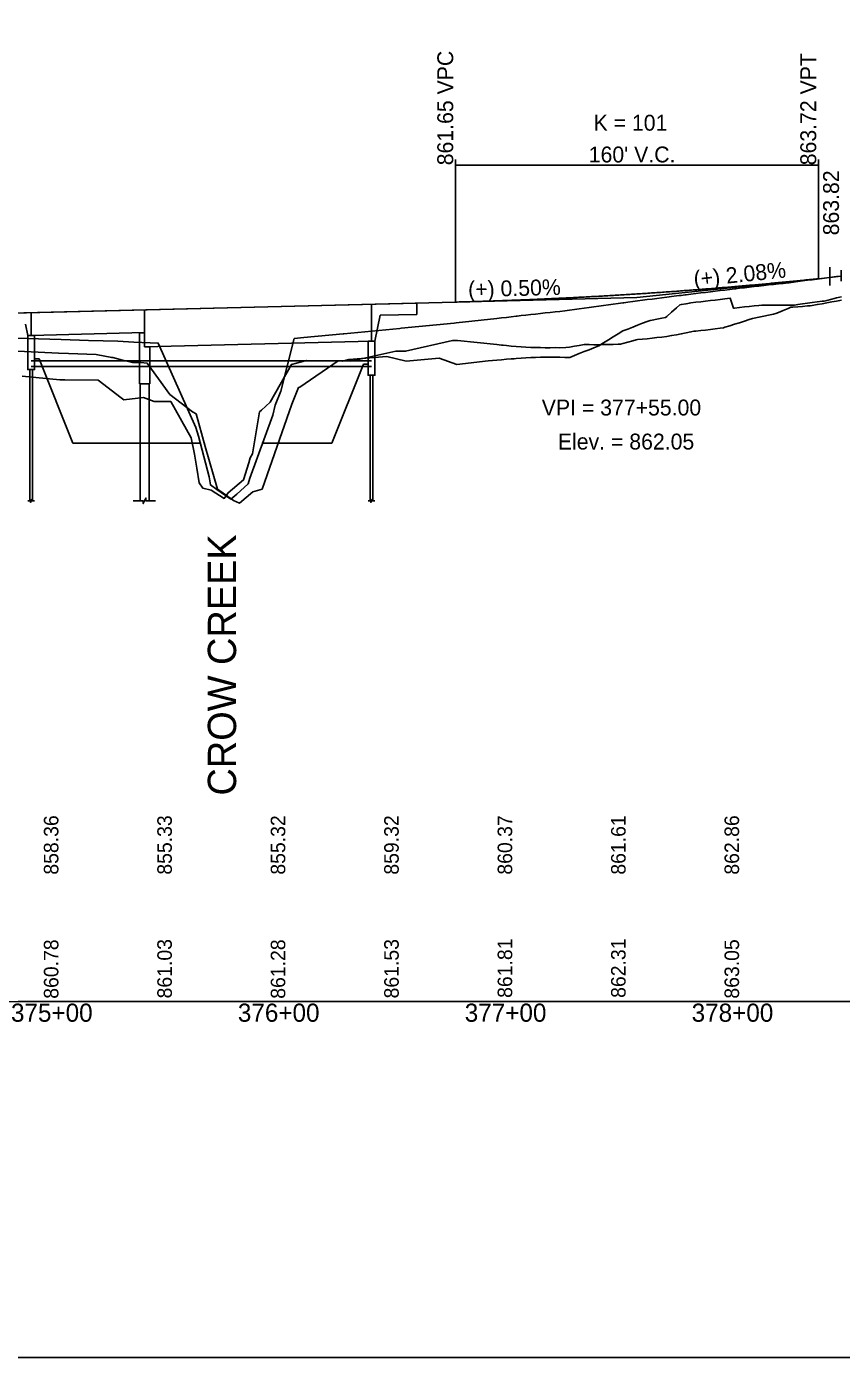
# Model space of a CAD drawing. Extents: x 1459978 to 1464152, y 1125650 to 1128602.
# Drawn here: x 1461940 to 1462299, y 1127502 to 1128089 of the extents above; entities that cross this region are included whole.
import ezdxf

# ---------------------------------------------------------------- set-up
doc = ezdxf.new("R2010")
doc.units = 0
for name, color, linetype in [('BR_CONCRETE', 7, 'Continuous'), ('BR_EXIST_GROUND_LT', 7, 'Continuous'), ('BR_EXIST_GROUND_RT', 7, 'Continuous'), ('BR_GROUND LINES', 7, 'Continuous'), ('BR_USER NOTES', 7, 'Continuous'), ('RD_DDB_GradeTX', 7, 'Continuous'), ('RD_DDB_Profile_EX', 7, 'Continuous'), ('RD_DDB_Profile_Lbl', 7, 'Continuous'), ('RD_DDB_Profile_PR', 7, 'Continuous'), ('RD_DDB_StaTX', 7, 'Continuous'), ('RD_DDB_StripGrade', 7, 'Continuous'), ('RD_DDB_VCLbl', 7, 'Continuous'), ('RD_GPK_Profile_Cell', 7, 'Continuous'), ('RD_SHT_ShtClip', 7, 'Continuous'), ('RD_SHT_TX', 7, 'Continuous')]:
    doc.layers.add(name, color=color, linetype=linetype)

msp = doc.modelspace()

# ---------------------------------------------------------------- linework, layer by layer
at = {"layer": 'BR_CONCRETE'}
for p, q in [((1461921.69, 1127962.22), (1462111.69, 1127966.97)), ((1461941.69, 1127952.72), (1461941.69, 1127962.72)), ((1461991.69, 1127947.72), (1461991.69, 1127963.97)), ((1462091.69, 1127950.22), (1462091.69, 1127966.47)), ((1462093.19, 1127950.14), (1462095.48, 1127961.57)), ((1462095.48, 1127961.57), (1462111.69, 1127961.97)), ((1462111.69, 1127966.97), (1462111.69, 1127961.97)), ((1461940.19, 1127952.64), (1461939.19, 1127957.66)), ((1461941.69, 1127952.72), (1461991.69, 1127953.97)), ((1461941.69, 1127952.72), (1461941.69, 1127952.64)), ((1461991.69, 1127947.72), (1462091.69, 1127950.22)), ((1462091.69, 1127950.22), (1462091.69, 1127950.14)), ((1461941.11, 1127937.4), (1461941.11, 1127879.76)), ((1461942.27, 1127937.4), (1461942.27, 1127879.76)), ((1462091.11, 1127935.14), (1462091.11, 1127879.76)), ((1462092.27, 1127935.14), (1462092.27, 1127879.76)), ((1461989.69, 1127879.76), (1461989.69, 1127931.39)), ((1461993.69, 1127879.76), (1461993.69, 1127931.39))]:
    msp.add_line(p, q, dxfattribs=at)
for points in [[(1461940.19, 1127952.64), (1461943.19, 1127952.64), (1461943.19, 1127937.64), (1461940.19, 1127937.64)], [(1461991.69, 1127947.64), (1461993.94, 1127947.64), (1461993.94, 1127931.39), (1461989.44, 1127931.39), (1461989.44, 1127953.86), (1461991.69, 1127953.86)], [(1462093.19, 1127950.14), (1462090.19, 1127950.14), (1462090.19, 1127935.14), (1462093.19, 1127935.14)]]:
    msp.add_lwpolyline(points, close=True, dxfattribs=at)
for points in [[(1461940.19, 1127879.76), (1461941.35, 1127879.76), (1461941.35, 1127879.07), (1461942.04, 1127880.46), (1461942.04, 1127879.76), (1461943.2, 1127879.76)], [(1461986.7, 1127879.76), (1461991.09, 1127879.76), (1461991.09, 1127878.56), (1461992.29, 1127880.96), (1461992.29, 1127879.76), (1461996.55, 1127879.76)], [(1462090.19, 1127879.76), (1462091.35, 1127879.76), (1462091.35, 1127879.07), (1462092.04, 1127880.46), (1462092.04, 1127879.76), (1462093.2, 1127879.76)]]:
    msp.add_lwpolyline(points, dxfattribs=at)
at = {"layer": 'BR_EXIST_GROUND_LT'}
msp.add_lwpolyline([(1461932.79, 1127945.88), (1461953.77, 1127944.88), (1461958.1, 1127944.67), (1461970.3, 1127944.33), (1461977.18, 1127942.96), (1461977.7, 1127942.94), (1461980.91, 1127942.11), (1461986.37, 1127940.81), (1461990, 1127940.72), (1461992.84, 1127940.43), (1462002.81, 1127926.71), (1462012.8, 1127918.95), (1462014.39, 1127918.07), (1462018.42, 1127903.69), (1462023.82, 1127884.85), (1462030.8, 1127879.93), (1462033.53, 1127878.8), (1462039.35, 1127883.8), (1462043.47, 1127884.98), (1462056.56, 1127922.32), (1462059.52, 1127929.8), (1462060.13, 1127929.88), (1462077.06, 1127941.53), (1462082.56, 1127941.39), (1462102.39, 1127945.74), (1462106.74, 1127945.71), (1462127.45, 1127950.42), (1462129.63, 1127950.45), (1462146.9, 1127948.65), (1462149.04, 1127948.43), (1462149.75, 1127948.36), (1462151.18, 1127948.19), (1462153.32, 1127947.96), (1462155.46, 1127947.76), (1462157.6, 1127947.62), (1462159.74, 1127947.51), (1462161.88, 1127947.42), (1462164.02, 1127947.35), (1462166.16, 1127947.3), (1462168.3, 1127947.28), (1462170.44, 1127947.28), (1462172.58, 1127947.3), (1462174.72, 1127947.29), (1462177.35, 1127947.31), (1462179, 1127947.57), (1462181.14, 1127947.93), (1462183.28, 1127948.31), (1462185.42, 1127948.68), (1462187.56, 1127948.64), (1462189.7, 1127948.62), (1462191.83, 1127948.62), (1462193.97, 1127948.64), (1462196.11, 1127948.68), (1462198.25, 1127948.74), (1462200.39, 1127948.82), (1462201.39, 1127948.87), (1462202.53, 1127949.17), (1462204.67, 1127949.76), (1462206.81, 1127950.36), (1462208.31, 1127950.8), (1462208.95, 1127950.85), (1462211.09, 1127951.04), (1462213.23, 1127951.25), (1462215.37, 1127951.49), (1462217.51, 1127951.74), (1462219.65, 1127952), (1462221.79, 1127952.29), (1462223.93, 1127952.6), (1462226.07, 1127952.98), (1462228.21, 1127953.38), (1462230.35, 1127953.79), (1462232.49, 1127954.22), (1462233.8, 1127954.5), (1462234.63, 1127954.58), (1462236.77, 1127954.81), (1462238.91, 1127955.06), (1462241.05, 1127955.32), (1462243.19, 1127955.6), (1462245.33, 1127955.9), (1462246.77, 1127956.11), (1462247.47, 1127956.31), (1462249.61, 1127956.96), (1462251.75, 1127957.62), (1462253.89, 1127958.3), (1462256.03, 1127958.99), (1462258.17, 1127959.7), (1462259.6, 1127960.19), (1462260.31, 1127960.32), (1462262.44, 1127960.74), (1462264.58, 1127961.18), (1462266.72, 1127961.63), (1462268.86, 1127962.09), (1462269.89, 1127962.32), (1462271, 1127962.79), (1462273.14, 1127963.7), (1462275.28, 1127964.62), (1462276.49, 1127965.12), (1462277.42, 1127965.18), (1462279.56, 1127965.33), (1462281.7, 1127965.5), (1462283.84, 1127965.69), (1462285.01, 1127965.79), (1462285.98, 1127965.95), (1462288.12, 1127966.31), (1462290.26, 1127966.68), (1462292.4, 1127967.07), (1462294.54, 1127967.46), (1462296.68, 1127967.87), (1462298.82, 1127968.29)], dxfattribs=at)
at = {"layer": 'BR_EXIST_GROUND_RT'}
msp.add_lwpolyline([(1461937.73, 1127934.7), (1461954.37, 1127933.18), (1461956.53, 1127933.17), (1461971.19, 1127932.99), (1461981.39, 1127925.22), (1461982.57, 1127924.33), (1461991.26, 1127925.32), (1461995.85, 1127923.63), (1462003.22, 1127923.6), (1462012.18, 1127907.51), (1462013.63, 1127900.38), (1462014.67, 1127894.14), (1462015.69, 1127887.65), (1462017.34, 1127885.37), (1462021.03, 1127884.54), (1462026.81, 1127880.86), (1462028.49, 1127883.34), (1462035.34, 1127889), (1462037.65, 1127896.48), (1462038.22, 1127898.7), (1462039.19, 1127900.5), (1462042.33, 1127918.96), (1462043.24, 1127919.74), (1462047.06, 1127923.23), (1462056.47, 1127939.95), (1462063.11, 1127941.71), (1462078.98, 1127941.36), (1462081.71, 1127942.08), (1462098.5, 1127943.39), (1462106.93, 1127941.38), (1462121.54, 1127942.66), (1462129.28, 1127939.92), (1462143.08, 1127941.47), (1462146.9, 1127941.82), (1462149.04, 1127942), (1462151.18, 1127942.16), (1462153.32, 1127942.31), (1462154.5, 1127942.38), (1462155.46, 1127942.46), (1462157.6, 1127942.62), (1462159.74, 1127942.77), (1462161.88, 1127942.9), (1462164.02, 1127943.01), (1462166.16, 1127943.11), (1462167.29, 1127943.15), (1462168.3, 1127943.16), (1462170.44, 1127943.15), (1462172.58, 1127943.13), (1462174.72, 1127943.09), (1462176.86, 1127943.03), (1462179.12, 1127942.95), (1462181.14, 1127943.8), (1462183.28, 1127944.68), (1462185.42, 1127945.54), (1462187.56, 1127946.39), (1462189.7, 1127947.22), (1462191.83, 1127948.09), (1462193.97, 1127949.43), (1462196.11, 1127950.75), (1462198.25, 1127952.06), (1462200.39, 1127953.37), (1462202.53, 1127954.67), (1462204.67, 1127955.44), (1462206.81, 1127956.29), (1462208.95, 1127957.26), (1462209.66, 1127957.58), (1462211.09, 1127958.07), (1462213.23, 1127958.8), (1462214.45, 1127959.21), (1462215.37, 1127959.4), (1462217.51, 1127959.84), (1462219.65, 1127960.27), (1462221.26, 1127960.6), (1462221.79, 1127961.07), (1462223.93, 1127962.94), (1462226.07, 1127964.82), (1462227.61, 1127966.18), (1462228.21, 1127966.29), (1462230.35, 1127966.69), (1462231.83, 1127966.96), (1462232.49, 1127967.04), (1462234.63, 1127967.29), (1462236.77, 1127967.54), (1462238.91, 1127967.79), (1462241.05, 1127968.04), (1462243.19, 1127968.3), (1462245.33, 1127968.55), (1462247.47, 1127968.81), (1462249.79, 1127969.09), (1462251.18, 1127964.72), (1462251.75, 1127964.78), (1462253.89, 1127965.02), (1462256.03, 1127965.25), (1462258.17, 1127965.48), (1462260.31, 1127965.7), (1462262.44, 1127965.92), (1462263.72, 1127966.05), (1462264.58, 1127966.05), (1462266.72, 1127966.07), (1462268.86, 1127966.08), (1462271, 1127966.08), (1462273.14, 1127966.08), (1462275.28, 1127966.08), (1462276.39, 1127966.07), (1462277.42, 1127966.07), (1462278.09, 1127966.06), (1462279.56, 1127966.27), (1462281.7, 1127966.57), (1462283.84, 1127966.87), (1462285.98, 1127967.16), (1462288.12, 1127967.45), (1462290.26, 1127967.73), (1462291.2, 1127967.85), (1462292.4, 1127968.16), (1462294.54, 1127968.7), (1462296.68, 1127969.25), (1462298.82, 1127969.78)], dxfattribs=at)
at = {"layer": 'BR_GROUND LINES'}
for p, q in [((1461943.19, 1127942.4), (1461945.19, 1127942.4)), ((1461945.19, 1127942.4), (1461960.04, 1127905.21)), ((1462088.19, 1127940.05), (1462074.26, 1127905.21)), ((1462090.19, 1127940.05), (1462088.19, 1127940.05)), ((1461960.04, 1127905.21), (1462016.39, 1127905.21)), ((1462043.37, 1127905.21), (1462074.26, 1127905.21))]:
    msp.add_line(p, q, dxfattribs=at)
at = {"layer": 'BR_USER NOTES'}
for p, q in [((1462293.69, 1127982.83), (1462293.69, 1127974.64)), ((1462298.69, 1127981.41), (1462298.69, 1127976.66)), ((1462293.69, 1127978.23), (1462298.69, 1127978.85)), ((1461941.69, 1127941.47), (1462091.69, 1127941.47)), ((1461941.69, 1127938.97), (1462091.69, 1127938.97))]:
    msp.add_line(p, q, dxfattribs=at)
at = {"layer": 'RD_DDB_GradeTX'}
for p in [(1462288.26, 1127977.67), (1462128.72, 1127967.4)]:
    msp.add_line(p, (1462208.69, 1127969.4), dxfattribs=at)
at = {"layer": 'RD_DDB_Profile_EX'}
msp.add_lwpolyline([(1461930.08, 1127951.68), (1461954.92, 1127950.9), (1461967, 1127950.52), (1461979.95, 1127950.11), (1461987, 1127949.79), (1461997.7, 1127949.31), (1462014.2, 1127912.05), (1462015.37, 1127908.21), (1462020.16, 1127890.3), (1462020.69, 1127886.78), (1462023.48, 1127884.83), (1462029.7, 1127880.53), (1462032.39, 1127882.69), (1462037.31, 1127887.34), (1462038.06, 1127889.81), (1462048.19, 1127917.6), (1462049.2, 1127921.95), (1462051.74, 1127928.12), (1462057.67, 1127951.32), (1462061.84, 1127951.72), (1462079.14, 1127953.35), (1462079.53, 1127953.39), (1462104.13, 1127955.76), (1462104.75, 1127955.83), (1462128.1, 1127958.09), (1462129.03, 1127958.21), (1462146.9, 1127960.19), (1462149.04, 1127960.43), (1462151.18, 1127960.67), (1462153.32, 1127960.91), (1462155.46, 1127961.19), (1462155.89, 1127961.24), (1462157.6, 1127961.43), (1462159.74, 1127961.67), (1462161.88, 1127961.9), (1462164.02, 1127962.14), (1462166.16, 1127962.37), (1462168.3, 1127962.61), (1462170.44, 1127962.84), (1462172.58, 1127963.07), (1462174.72, 1127963.3), (1462176.86, 1127963.54), (1462177.95, 1127963.65), (1462179, 1127963.81), (1462181.14, 1127964.14), (1462183.28, 1127964.43), (1462185.42, 1127964.72), (1462187.56, 1127965.01), (1462189.7, 1127965.3), (1462191.83, 1127965.59), (1462193.97, 1127965.88), (1462196.11, 1127966.16), (1462198.25, 1127966.45), (1462200.39, 1127966.73), (1462202.53, 1127967.01), (1462202.92, 1127967.06), (1462204.67, 1127967.32), (1462206.81, 1127967.64), (1462208.95, 1127967.92), (1462211.09, 1127968.19), (1462213.23, 1127968.47), (1462215.37, 1127968.74), (1462217.51, 1127969.01), (1462219.65, 1127969.28), (1462221.79, 1127969.55), (1462223.93, 1127969.82), (1462226.07, 1127970.09), (1462227.25, 1127970.24), (1462228.21, 1127970.36), (1462229.97, 1127970.58), (1462230.35, 1127970.63), (1462232.49, 1127970.89), (1462234.63, 1127971.16), (1462236.77, 1127971.42), (1462238.91, 1127971.68), (1462241.05, 1127971.94), (1462243.19, 1127972.2), (1462245.33, 1127972.45), (1462247.47, 1127972.71), (1462249.61, 1127972.96), (1462251.75, 1127973.21), (1462252.21, 1127973.27), (1462253.89, 1127973.47), (1462255.39, 1127973.65), (1462256.03, 1127973.72), (1462258.17, 1127973.97), (1462260.31, 1127974.21), (1462262.44, 1127974.45), (1462264.58, 1127974.7), (1462266.72, 1127974.94), (1462268.86, 1127975.18), (1462271, 1127975.41), (1462273.14, 1127975.65), (1462275.28, 1127975.88), (1462275.72, 1127975.93), (1462277.67, 1127976.19), (1462279.56, 1127976.44), (1462281.7, 1127976.72), (1462283.84, 1127976.99), (1462285.98, 1127977.26), (1462288.12, 1127977.53), (1462290.26, 1127977.8), (1462292.4, 1127978.07), (1462294.54, 1127978.34), (1462296.68, 1127978.6), (1462298.82, 1127978.87)], dxfattribs=at)
at = {"layer": 'RD_DDB_Profile_PR'}
for p, q in [((1462288.69, 1127977.71), (1462293.69, 1127978.23)), ((1461933.69, 1127962.52), (1462128.69, 1127967.4))]:
    msp.add_line(p, q, dxfattribs=at)
msp.add_spline([(1462128.69, 1127967.4), (1462131.89, 1127967.48), (1462135.09, 1127967.57), (1462138.29, 1127967.66), (1462141.49, 1127967.76), (1462144.69, 1127967.86), (1462147.89, 1127967.97), (1462151.09, 1127968.08), (1462154.29, 1127968.2), (1462157.49, 1127968.32), (1462160.69, 1127968.45), (1462163.89, 1127968.58), (1462167.09, 1127968.72), (1462170.29, 1127968.87), (1462173.49, 1127969.01), (1462176.69, 1127969.17), (1462179.89, 1127969.33), (1462183.09, 1127969.49), (1462186.29, 1127969.66), (1462189.49, 1127969.83), (1462192.69, 1127970.01), (1462195.89, 1127970.19), (1462199.09, 1127970.38), (1462202.29, 1127970.57), (1462205.49, 1127970.77), (1462208.69, 1127970.98), (1462211.89, 1127971.19), (1462215.09, 1127971.4), (1462218.29, 1127971.62), (1462221.49, 1127971.84), (1462224.69, 1127972.07), (1462227.89, 1127972.31), (1462231.09, 1127972.55), (1462234.29, 1127972.79), (1462237.49, 1127973.04), (1462240.69, 1127973.29), (1462243.89, 1127973.55), (1462247.09, 1127973.82), (1462250.29, 1127974.09), (1462253.49, 1127974.36), (1462256.69, 1127974.64), (1462259.89, 1127974.92), (1462263.09, 1127975.21), (1462266.29, 1127975.51), (1462269.49, 1127975.81), (1462272.69, 1127976.11), (1462275.89, 1127976.42), (1462279.09, 1127976.74), (1462282.29, 1127977.06), (1462285.49, 1127977.38), (1462288.69, 1127977.71)], degree=3, dxfattribs=at)
at = {"layer": 'RD_DDB_VCLbl'}
for p, q in [((1462128.69, 1128030.21), (1462128.69, 1127967.4)), ((1462128.69, 1128027.71), (1462288.69, 1128027.71)), ((1462288.69, 1128030.21), (1462288.69, 1127977.71))]:
    msp.add_line(p, q, dxfattribs=at)
at = {"layer": 'RD_GPK_Profile_Cell'}
msp.add_line((1460062.18, 1127659.12), (1464151.92, 1127659.12), dxfattribs=at)
at = {"layer": 'RD_SHT_ShtClip'}
msp.add_lwpolyline([(1461075.85, 1128602.16), (1462875.85, 1128602.16), (1462875.85, 1127502.16), (1461075.85, 1127502.16)], close=True, dxfattribs=at)

# ---------------------------------------------------------------- texts
at = {"layer": 'RD_DDB_GradeTX'}
for s, rotation, p in [('(+) 2.08%', 5.9336, (1462234.02, 1127974.04)), ('(+) 0.50%', 1.4321, (1462134.34, 1127969.54))]:
    msp.add_text(s, height=7, rotation=rotation, dxfattribs=at).set_placement(p)
at = {"layer": 'RD_DDB_Profile_Lbl'}
msp.add_text('863.82', height=7, rotation=90, dxfattribs=at).set_placement((1462297.73, 1127996.82))
for s, p in [('VPI = 377+55.00', (1462166.73, 1127917.4)), ('Elev. = 862.05', (1462173.83, 1127902.4))]:
    msp.add_text(s, height=7, dxfattribs=at).set_placement(p)
at = {"layer": 'RD_DDB_StaTX'}
for s, p in [('375+00', (1461932.79, 1127650.12)), ('376+00', (1462032.79, 1127650.12)), ('377+00', (1462132.79, 1127650.12)), ('378+00', (1462232.79, 1127650.12))]:
    msp.add_text(s, height=8, dxfattribs=at).set_placement(p)
at = {"layer": 'RD_DDB_StripGrade'}
for s, height, p in [('861.65 VPC', 7, (1462127.69, 1128027.71)), ('863.72 VPT', 7, (1462287.69, 1128027.71)), ('858.36', 6.4, (1461953.69, 1127714.97)), ('855.33', 6.4, (1462003.69, 1127714.97)), ('855.32', 6.4, (1462053.69, 1127714.97)), ('859.32', 6.4, (1462103.69, 1127714.97)), ('860.37', 6.4, (1462153.69, 1127714.97)), ('861.61', 6.4, (1462203.69, 1127714.97)), ('862.86', 6.4, (1462253.69, 1127714.97)), ('860.78', 6.4, (1461953.69, 1127660.26)), ('861.03', 6.4, (1462003.69, 1127660.41)), ('861.28', 6.4, (1462053.69, 1127660.26)), ('861.53', 6.4, (1462103.69, 1127660.41)), ('861.81', 6.4, (1462153.69, 1127660.65)), ('862.31', 6.4, (1462203.69, 1127660.65)), ('863.05', 6.4, (1462253.69, 1127660.31))]:
    msp.add_text(s, height=height, rotation=90, dxfattribs=at).set_placement(p)
at = {"layer": 'RD_DDB_VCLbl'}
for s, p in [('K = 101', (1462189.56, 1128042.96)), ("160' V.C.", (1462187.44, 1128028.96))]:
    msp.add_text(s, height=7, dxfattribs=at).set_placement(p)
at = {"layer": 'RD_SHT_TX'}
msp.add_text('CROW CREEK', height=12.5, rotation=90, dxfattribs=at).set_placement((1462032.03, 1127749.85))

doc.saveas('drawing.dxf')
